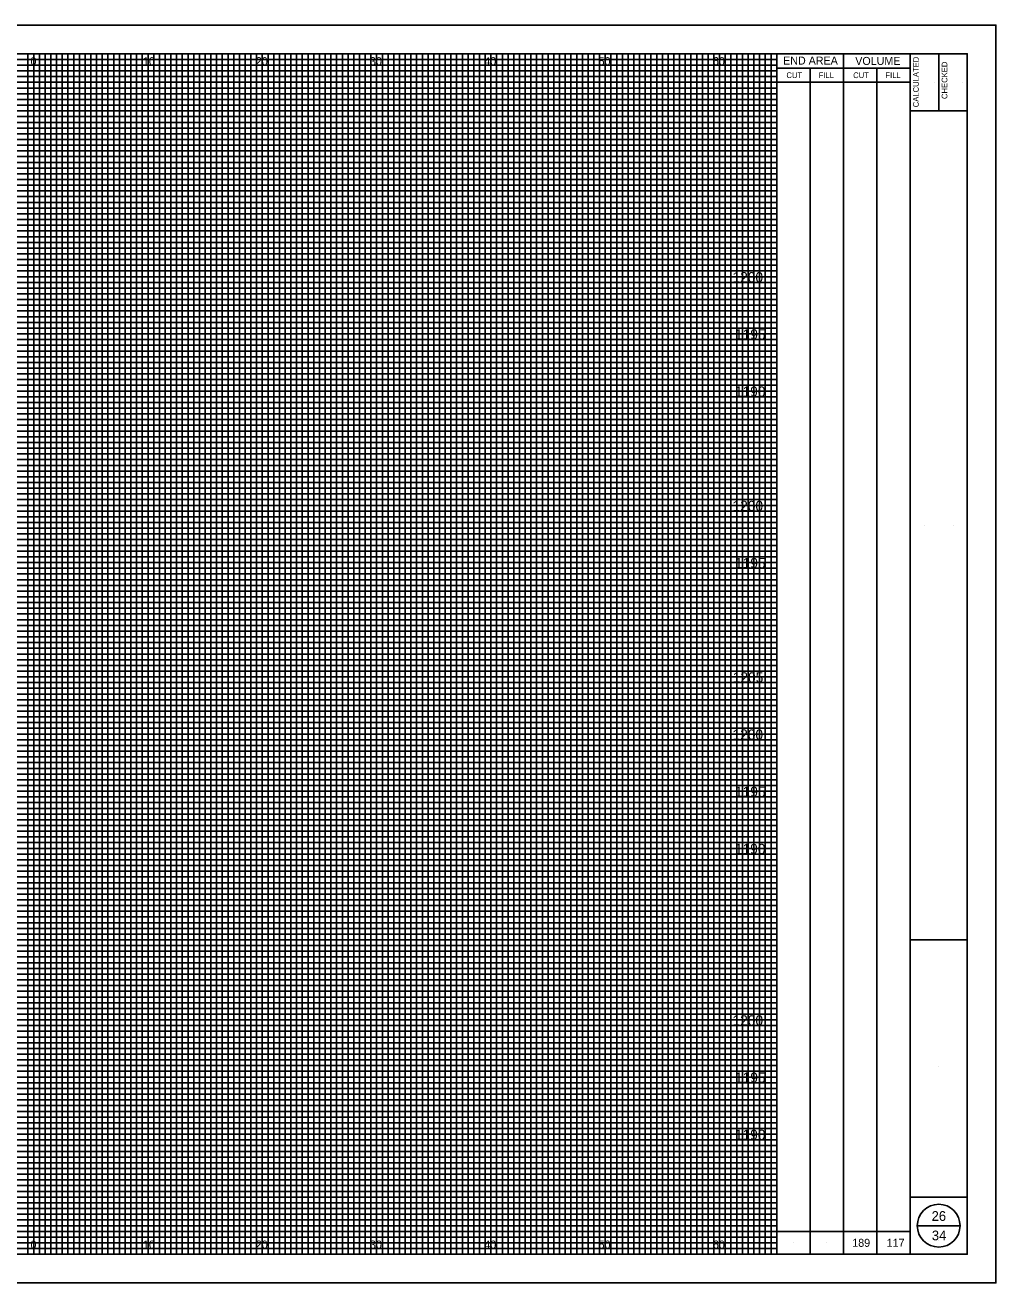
# Model space of a CAD drawing. Extents: x -10 to 160, y -13 to 1488.
# Drawn here: x 75.1 to 160, y 1032.5 to 1142.5 of the extents above; entities that cross this region are included whole.
import ezdxf

# ---------------------------------------------------------------- set-up
doc = ezdxf.new("R2010")
doc.units = 0
for name, color, linetype in [('DR_X_Storm_Sewer', 7, 'Continuous'), ('GK_Cells', 7, 'Continuous'), ('PF_P_Sta_Elev_Text', 7, 'Continuous'), ('PF_X_Ground_Line', 7, 'Continuous'), ('PV_P_EOP', 7, 'Continuous'), ('PV_P_Shoulder', 7, 'Continuous')]:
    doc.layers.add(name, color=color, linetype=linetype)

msp = doc.modelspace()

# ---------------------------------------------------------------- linework, layer by layer
at = {"layer": 'GK_Cells'}
for p, q in [((152.5, 1035), (152.5, 1140)), ((155, 1140), (155, 1135)), ((152.5, 1135), (157.5, 1135)), ((152.5, 1062.5), (157.5, 1062.5)), ((152.5, 1040), (157.5, 1040))]:
    msp.add_line(p, q, dxfattribs=at)
msp.add_lwpolyline([(0, 1140), (157.5, 1140), (157.5, 1035), (0, 1035)], close=True, dxfattribs=at)
at = {"layer": 'PF_P_Sta_Elev_Text'}
msp.add_lwpolyline([(-10, 1032.5), (160, 1032.5), (160, 1142.5), (-10, 1142.5)], close=True, dxfattribs=at)
at = {"layer": 'PF_X_Ground_Line'}
for p, q in [((140.83, 1035), (140.83, 1140)), ((146.67, 1035), (146.67, 1140)), ((140.83, 1138.75), (152.5, 1138.75)), ((143.75, 1035), (143.75, 1138.75)), ((149.58, 1035), (149.58, 1138.75)), ((140.83, 1137.5), (152.5, 1137.5)), ((154.6, 1137.52), (154.6, 1137.52)), ((157.1, 1137.52), (157.1, 1137.52)), ((153.75, 1098.75), (153.75, 1098.75)), ((156.26, 1098.75), (156.26, 1098.75)), ((155, 1051.46), (155, 1051.46)), ((153.12, 1037.5), (156.88, 1037.5)), ((155, 1037.92), (155, 1037.92)), ((140.83, 1037), (152.5, 1037)), ((155, 1036.22), (155, 1036.22)), ((142.29, 1036), (142.29, 1036)), ((145.21, 1036), (145.21, 1036)), ((148.12, 1036), (148.12, 1036)), ((151.04, 1036), (151.04, 1036))]:
    msp.add_line(p, q, dxfattribs=at)
msp.add_circle((155, 1037.5), 1.87, dxfattribs=at)
at = {"layer": 'PV_P_EOP'}
for p, q in [((75.33, 1035), (75.33, 1140)), ((76.33, 1035), (76.33, 1140)), ((76.83, 1035), (76.83, 1140)), ((77.33, 1035), (77.33, 1140)), ((77.83, 1035), (77.83, 1140)), ((78.33, 1035), (78.33, 1140)), ((78.83, 1035), (78.83, 1140)), ((79.33, 1035), (79.33, 1140)), ((79.83, 1035), (79.83, 1140)), ((80.33, 1035), (80.33, 1140)), ((81.33, 1035), (81.33, 1140)), ((81.83, 1035), (81.83, 1140)), ((82.33, 1035), (82.33, 1140)), ((82.83, 1035), (82.83, 1140)), ((83.33, 1035), (83.33, 1140)), ((83.83, 1035), (83.83, 1140)), ((84.33, 1035), (84.33, 1140)), ((84.83, 1035), (84.83, 1140)), ((85.33, 1035), (85.33, 1140)), ((86.33, 1035), (86.33, 1140)), ((86.83, 1035), (86.83, 1140)), ((87.33, 1035), (87.33, 1140)), ((87.83, 1035), (87.83, 1140)), ((88.33, 1035), (88.33, 1140)), ((88.83, 1035), (88.83, 1140)), ((89.33, 1035), (89.33, 1140)), ((89.83, 1035), (89.83, 1140)), ((90.33, 1035), (90.33, 1140)), ((91.33, 1035), (91.33, 1140)), ((91.83, 1035), (91.83, 1140)), ((92.33, 1035), (92.33, 1140)), ((92.83, 1035), (92.83, 1140)), ((93.33, 1035), (93.33, 1140)), ((93.83, 1035), (93.83, 1140)), ((94.33, 1035), (94.33, 1140)), ((94.83, 1035), (94.83, 1140)), ((95.33, 1035), (95.33, 1140)), ((96.33, 1035), (96.33, 1140)), ((96.83, 1035), (96.83, 1140)), ((97.33, 1035), (97.33, 1140)), ((97.83, 1035), (97.83, 1140)), ((98.33, 1035), (98.33, 1140)), ((98.83, 1035), (98.83, 1140)), ((99.33, 1035), (99.33, 1140)), ((99.83, 1035), (99.83, 1140)), ((100.33, 1035), (100.33, 1140)), ((101.33, 1035), (101.33, 1140)), ((101.83, 1035), (101.83, 1140)), ((102.33, 1035), (102.33, 1140)), ((102.83, 1035), (102.83, 1140)), ((103.33, 1035), (103.33, 1140)), ((103.83, 1035), (103.83, 1140)), ((104.33, 1035), (104.33, 1140)), ((104.83, 1035), (104.83, 1140)), ((105.33, 1035), (105.33, 1140)), ((106.33, 1035), (106.33, 1140)), ((106.83, 1035), (106.83, 1140)), ((107.33, 1035), (107.33, 1140)), ((107.83, 1035), (107.83, 1140)), ((108.33, 1035), (108.33, 1140)), ((108.83, 1035), (108.83, 1140)), ((109.33, 1035), (109.33, 1140)), ((109.83, 1035), (109.83, 1140)), ((110.33, 1035), (110.33, 1140)), ((111.33, 1035), (111.33, 1140)), ((111.83, 1035), (111.83, 1140)), ((112.33, 1035), (112.33, 1140)), ((112.83, 1035), (112.83, 1140)), ((113.33, 1035), (113.33, 1140)), ((113.83, 1035), (113.83, 1140)), ((114.33, 1035), (114.33, 1140)), ((114.83, 1035), (114.83, 1140)), ((115.33, 1035), (115.33, 1140)), ((116.33, 1035), (116.33, 1140)), ((116.83, 1035), (116.83, 1140)), ((117.33, 1035), (117.33, 1140)), ((117.83, 1035), (117.83, 1140)), ((118.33, 1035), (118.33, 1140)), ((118.83, 1035), (118.83, 1140)), ((119.33, 1035), (119.33, 1140)), ((119.83, 1035), (119.83, 1140)), ((120.33, 1035), (120.33, 1140)), ((121.33, 1035), (121.33, 1140)), ((121.83, 1035), (121.83, 1140)), ((122.33, 1035), (122.33, 1140)), ((122.83, 1035), (122.83, 1140)), ((123.33, 1035), (123.33, 1140)), ((123.83, 1035), (123.83, 1140)), ((124.33, 1035), (124.33, 1140)), ((124.83, 1035), (124.83, 1140)), ((125.33, 1035), (125.33, 1140)), ((126.33, 1035), (126.33, 1140)), ((126.83, 1035), (126.83, 1140)), ((127.33, 1035), (127.33, 1140)), ((127.83, 1035), (127.83, 1140)), ((128.33, 1035), (128.33, 1140)), ((128.83, 1035), (128.83, 1140)), ((129.33, 1035), (129.33, 1140)), ((129.83, 1035), (129.83, 1140)), ((130.33, 1035), (130.33, 1140)), ((131.33, 1035), (131.33, 1140)), ((131.83, 1035), (131.83, 1140)), ((132.33, 1035), (132.33, 1140)), ((132.83, 1035), (132.83, 1140)), ((133.33, 1035), (133.33, 1140)), ((133.83, 1035), (133.83, 1140)), ((134.33, 1035), (134.33, 1140)), ((134.83, 1035), (134.83, 1140)), ((135.33, 1035), (135.33, 1140)), ((136.33, 1035), (136.33, 1140)), ((136.83, 1035), (136.83, 1140)), ((137.33, 1035), (137.33, 1140)), ((137.83, 1035), (137.83, 1140)), ((138.33, 1035), (138.33, 1140)), ((138.83, 1035), (138.83, 1140)), ((139.33, 1035), (139.33, 1140)), ((139.83, 1035), (139.83, 1140)), ((140.33, 1035), (140.33, 1140)), ((5.83, 1139.5), (140.83, 1139.5)), ((5.83, 1139), (140.83, 1139)), ((5.83, 1138.5), (140.83, 1138.5)), ((5.83, 1138), (140.83, 1138)), ((5.83, 1137.5), (140.83, 1137.5)), ((5.83, 1137), (140.83, 1137)), ((5.83, 1136.5), (140.83, 1136.5)), ((5.83, 1136), (140.83, 1136)), ((5.83, 1135.5), (140.83, 1135.5)), ((5.83, 1134.5), (140.83, 1134.5)), ((5.83, 1134), (140.83, 1134)), ((5.83, 1133.5), (140.83, 1133.5)), ((5.83, 1133), (140.83, 1133)), ((5.83, 1132.5), (140.83, 1132.5)), ((5.83, 1132), (140.83, 1132)), ((5.83, 1131.5), (140.83, 1131.5)), ((5.83, 1131), (140.83, 1131)), ((5.83, 1130.5), (140.83, 1130.5)), ((5.83, 1129.5), (140.83, 1129.5)), ((5.83, 1129), (140.83, 1129)), ((5.83, 1128.5), (140.83, 1128.5)), ((5.83, 1128), (140.83, 1128)), ((5.83, 1127.5), (140.83, 1127.5)), ((5.83, 1127), (140.83, 1127)), ((5.83, 1126.5), (140.83, 1126.5)), ((5.83, 1126), (140.83, 1126)), ((5.83, 1125.5), (140.83, 1125.5)), ((5.83, 1124.5), (140.83, 1124.5)), ((5.83, 1124), (140.83, 1124)), ((5.83, 1123.5), (140.83, 1123.5)), ((5.83, 1123), (140.83, 1123)), ((5.83, 1122.5), (140.83, 1122.5)), ((5.83, 1122), (140.83, 1122)), ((5.83, 1121.5), (140.83, 1121.5)), ((5.83, 1121), (140.83, 1121)), ((5.83, 1120.5), (140.83, 1120.5)), ((5.83, 1119.5), (140.83, 1119.5)), ((5.83, 1119), (140.83, 1119)), ((5.83, 1118.5), (140.83, 1118.5)), ((5.83, 1118), (140.83, 1118)), ((5.83, 1117.5), (140.83, 1117.5)), ((5.83, 1117), (140.83, 1117)), ((5.83, 1116.5), (140.83, 1116.5)), ((5.83, 1116), (140.83, 1116)), ((5.83, 1115.5), (140.83, 1115.5)), ((5.83, 1114.5), (140.83, 1114.5)), ((5.83, 1114), (140.83, 1114)), ((5.83, 1113.5), (140.83, 1113.5)), ((5.83, 1113), (140.83, 1113)), ((5.83, 1112.5), (140.83, 1112.5)), ((5.83, 1112), (140.83, 1112)), ((5.83, 1111.5), (140.83, 1111.5)), ((5.83, 1111), (140.83, 1111)), ((5.83, 1110.5), (140.83, 1110.5)), ((5.83, 1109.5), (140.83, 1109.5)), ((5.83, 1109), (140.83, 1109)), ((5.83, 1108.5), (140.83, 1108.5)), ((5.83, 1108), (140.83, 1108)), ((5.83, 1107.5), (140.83, 1107.5)), ((5.83, 1107), (140.83, 1107)), ((5.83, 1106.5), (140.83, 1106.5)), ((5.83, 1106), (140.83, 1106)), ((5.83, 1105.5), (140.83, 1105.5)), ((5.83, 1104.5), (140.83, 1104.5)), ((5.83, 1104), (140.83, 1104)), ((5.83, 1103.5), (140.83, 1103.5)), ((5.83, 1103), (140.83, 1103)), ((5.83, 1102.5), (140.83, 1102.5)), ((5.83, 1102), (140.83, 1102)), ((5.83, 1101.5), (140.83, 1101.5)), ((5.83, 1101), (140.83, 1101)), ((5.83, 1100.5), (140.83, 1100.5)), ((5.83, 1099.5), (140.83, 1099.5)), ((5.83, 1099), (140.83, 1099)), ((5.83, 1098.5), (140.83, 1098.5)), ((5.83, 1098), (140.83, 1098)), ((5.83, 1097.5), (140.83, 1097.5)), ((5.83, 1097), (140.83, 1097)), ((5.83, 1096.5), (140.83, 1096.5)), ((5.83, 1096), (140.83, 1096)), ((5.83, 1095.5), (140.83, 1095.5)), ((5.83, 1094.5), (140.83, 1094.5)), ((5.83, 1094), (140.83, 1094)), ((5.83, 1093.5), (140.83, 1093.5)), ((5.83, 1093), (140.83, 1093)), ((5.83, 1092.5), (140.83, 1092.5)), ((5.83, 1092), (140.83, 1092)), ((5.83, 1091.5), (140.83, 1091.5)), ((5.83, 1091), (140.83, 1091)), ((5.83, 1090.5), (140.83, 1090.5)), ((5.83, 1089.5), (140.83, 1089.5)), ((5.83, 1089), (140.83, 1089)), ((5.83, 1088.5), (140.83, 1088.5)), ((5.83, 1088), (140.83, 1088)), ((5.83, 1087.5), (140.83, 1087.5)), ((5.83, 1087), (140.83, 1087)), ((5.83, 1086.5), (140.83, 1086.5)), ((5.83, 1086), (140.83, 1086)), ((5.83, 1085.5), (140.83, 1085.5)), ((5.83, 1084.5), (140.83, 1084.5)), ((5.83, 1084), (140.83, 1084)), ((5.83, 1083.5), (140.83, 1083.5)), ((5.83, 1083), (140.83, 1083)), ((5.83, 1082.5), (140.83, 1082.5)), ((5.83, 1082), (140.83, 1082)), ((5.83, 1081.5), (140.83, 1081.5)), ((5.83, 1081), (140.83, 1081)), ((5.83, 1080.5), (140.83, 1080.5)), ((5.83, 1079.5), (140.83, 1079.5)), ((5.83, 1079), (140.83, 1079)), ((5.83, 1078.5), (140.83, 1078.5)), ((5.83, 1078), (140.83, 1078)), ((5.83, 1077.5), (140.83, 1077.5)), ((5.83, 1077), (140.83, 1077)), ((5.83, 1076.5), (140.83, 1076.5)), ((5.83, 1076), (140.83, 1076)), ((5.83, 1075.5), (140.83, 1075.5)), ((5.83, 1074.5), (140.83, 1074.5)), ((5.83, 1074), (140.83, 1074)), ((5.83, 1073.5), (140.83, 1073.5)), ((5.83, 1073), (140.83, 1073)), ((5.83, 1072.5), (140.83, 1072.5)), ((5.83, 1072), (140.83, 1072)), ((5.83, 1071.5), (140.83, 1071.5)), ((5.83, 1071), (140.83, 1071)), ((5.83, 1070.5), (140.83, 1070.5)), ((5.83, 1069.5), (140.83, 1069.5)), ((5.83, 1069), (140.83, 1069)), ((5.83, 1068.5), (140.83, 1068.5)), ((5.83, 1068), (140.83, 1068)), ((5.83, 1067.5), (140.83, 1067.5)), ((5.83, 1067), (140.83, 1067)), ((5.83, 1066.5), (140.83, 1066.5)), ((5.83, 1066), (140.83, 1066)), ((5.83, 1065.5), (140.83, 1065.5)), ((5.83, 1064.5), (140.83, 1064.5)), ((5.83, 1064), (140.83, 1064)), ((5.83, 1063.5), (140.83, 1063.5)), ((5.83, 1063), (140.83, 1063)), ((5.83, 1062.5), (140.83, 1062.5)), ((5.83, 1062), (140.83, 1062)), ((5.83, 1061.5), (140.83, 1061.5)), ((5.83, 1061), (140.83, 1061)), ((5.83, 1060.5), (140.83, 1060.5)), ((5.83, 1059.5), (140.83, 1059.5)), ((5.83, 1059), (140.83, 1059)), ((5.83, 1058.5), (140.83, 1058.5)), ((5.83, 1058), (140.83, 1058)), ((5.83, 1057.5), (140.83, 1057.5)), ((5.83, 1057), (140.83, 1057)), ((5.83, 1056.5), (140.83, 1056.5)), ((5.83, 1056), (140.83, 1056)), ((5.83, 1055.5), (140.83, 1055.5)), ((5.83, 1054.5), (140.83, 1054.5)), ((5.83, 1054), (140.83, 1054)), ((5.83, 1053.5), (140.83, 1053.5)), ((5.83, 1053), (140.83, 1053)), ((5.83, 1052.5), (140.83, 1052.5)), ((5.83, 1052), (140.83, 1052)), ((5.83, 1051.5), (140.83, 1051.5)), ((5.83, 1051), (140.83, 1051)), ((5.83, 1050.5), (140.83, 1050.5)), ((5.83, 1049.5), (140.83, 1049.5)), ((5.83, 1049), (140.83, 1049)), ((5.83, 1048.5), (140.83, 1048.5)), ((5.83, 1048), (140.83, 1048)), ((5.83, 1047.5), (140.83, 1047.5)), ((5.83, 1047), (140.83, 1047)), ((5.83, 1046.5), (140.83, 1046.5)), ((5.83, 1046), (140.83, 1046)), ((5.83, 1045.5), (140.83, 1045.5)), ((5.83, 1044.5), (140.83, 1044.5)), ((5.83, 1044), (140.83, 1044)), ((5.83, 1043.5), (140.83, 1043.5)), ((5.83, 1043), (140.83, 1043)), ((5.83, 1042.5), (140.83, 1042.5)), ((5.83, 1042), (140.83, 1042)), ((5.83, 1041.5), (140.83, 1041.5)), ((5.83, 1041), (140.83, 1041)), ((5.83, 1040.5), (140.83, 1040.5)), ((5.83, 1039.5), (140.83, 1039.5)), ((5.83, 1039), (140.83, 1039)), ((5.83, 1038.5), (140.83, 1038.5)), ((5.83, 1038), (140.83, 1038)), ((5.83, 1037.5), (140.83, 1037.5)), ((5.83, 1037), (140.83, 1037)), ((5.83, 1036.5), (140.83, 1036.5)), ((5.83, 1036), (140.83, 1036)), ((5.83, 1035.5), (140.83, 1035.5))]:
    msp.add_line(p, q, dxfattribs=at)
at = {"layer": 'PV_P_Shoulder'}
for p, q in [((75.83, 1035), (75.83, 1140)), ((80.83, 1035), (80.83, 1140)), ((85.83, 1035), (85.83, 1140)), ((90.83, 1035), (90.83, 1140)), ((95.83, 1035), (95.83, 1140)), ((100.83, 1035), (100.83, 1140)), ((105.83, 1035), (105.83, 1140)), ((110.83, 1035), (110.83, 1140)), ((115.83, 1035), (115.83, 1140)), ((120.83, 1035), (120.83, 1140)), ((125.83, 1035), (125.83, 1140)), ((130.83, 1035), (130.83, 1140)), ((135.83, 1035), (135.83, 1140)), ((5.83, 1135), (140.83, 1135)), ((5.83, 1130), (140.83, 1130)), ((5.83, 1125), (140.83, 1125)), ((5.83, 1120), (140.83, 1120)), ((5.83, 1115), (140.83, 1115)), ((5.83, 1110), (140.83, 1110)), ((5.83, 1105), (140.83, 1105)), ((5.83, 1100), (140.83, 1100)), ((5.83, 1095), (140.83, 1095)), ((5.83, 1090), (140.83, 1090)), ((5.83, 1085), (140.83, 1085)), ((5.83, 1080), (140.83, 1080)), ((5.83, 1075), (140.83, 1075)), ((5.83, 1070), (140.83, 1070)), ((5.83, 1065), (140.83, 1065)), ((5.83, 1060), (140.83, 1060)), ((5.83, 1055), (140.83, 1055)), ((5.83, 1050), (140.83, 1050)), ((5.83, 1045), (140.83, 1045)), ((5.83, 1040), (140.83, 1040))]:
    msp.add_line(p, q, dxfattribs=at)

# ---------------------------------------------------------------- texts
at = {"layer": 'DR_X_Storm_Sewer'}
for s, height, p in [('0', 0.7, (75.55, 1139)), ('0', 0.7, (75.55, 1139)), ('10', 0.7, (85.39, 1139)), ('20', 0.7, (95.26, 1139)), ('30', 0.7, (105.25, 1139)), ('40', 0.7, (115.25, 1139)), ('50', 0.7, (125.25, 1139)), ('60', 0.7, (135.25, 1139)), ('1200', 0.9, (136.96, 1120)), ('1195', 0.9, (137.18, 1115)), ('1190', 0.9, (137.17, 1110)), ('1200', 0.9, (136.96, 1100)), ('1195', 0.9, (137.18, 1095)), ('1205', 0.9, (136.98, 1085)), ('1200', 0.9, (136.96, 1080)), ('1195', 0.9, (137.18, 1075)), ('1190', 0.9, (137.17, 1070)), ('1200', 0.9, (136.96, 1055)), ('1195', 0.9, (137.18, 1050)), ('1190', 0.9, (137.17, 1045)), ('26', 0.85, (154.38, 1037.92)), ('0', 0.7, (75.55, 1035.5)), ('0', 0.7, (75.55, 1035.5)), ('10', 0.7, (85.39, 1035.5)), ('20', 0.7, (95.26, 1035.5)), ('30', 0.7, (105.25, 1035.5)), ('40', 0.7, (115.25, 1035.5)), ('50', 0.7, (125.25, 1035.5)), ('60', 0.7, (135.25, 1035.5)), ('189', 0.7, (147.44, 1035.65)), ('117', 0.7, (150.45, 1035.65)), ('34', 0.85, (154.4, 1036.22))]:
    msp.add_text(s, height=height, dxfattribs=at).set_placement(p)
at = {"layer": 'PF_X_Ground_Line'}
for s, height, p in [('END AREA', 0.7, (141.39, 1139.05)), ('VOLUME', 0.7, (147.7, 1139.02)), ('CUT', 0.5, (141.68, 1137.87)), ('FILL', 0.5, (144.5, 1137.87)), ('CUT', 0.5, (147.52, 1137.87)), ('FILL', 0.5, (150.34, 1137.87))]:
    msp.add_text(s, height=height, dxfattribs=at).set_placement(p)
for s, p in [('CALCULATED', (153.26, 1135.32)), ('CHECKED', (155.76, 1136.04))]:
    msp.add_text(s, height=0.5, rotation=90, dxfattribs=at).set_placement(p)

doc.saveas('drawing.dxf')
